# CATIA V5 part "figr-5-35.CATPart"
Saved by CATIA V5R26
Part number: Part1
Bounding box of the stored display mesh (mm): x -39.481 to 85.69, y 0 to 131.399, z 0 to 44
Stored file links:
  D:\_Deepak\CATIA\CATIA V5-6R2016_Deepak\Resources\Part files\Partfiles\c05_catia_v5_6r2016_prt\figr-5-35.CATPart
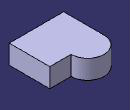
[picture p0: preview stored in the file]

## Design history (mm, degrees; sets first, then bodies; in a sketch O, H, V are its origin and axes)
Body1 (main body)
  Sketch1 on xy-plane, origin (0, 0, 0), H (1, 0, 0), V (0, 1, 0)
    point P1 (-39.4814, 0)
    line L1 (-39.4814, 0) -> (36.6898, 0)
    line L2 (36.6898, 0) -> (36.6898, 93.3015)
    arc A1 centre (-1.4186, 93.3015) radius 38.1084 from (36.6898, 93.3015) to (-39.4814, 95.1659) ccw
    line L3 (-39.4814, 95.1659) -> (-39.4814, 0)
    coincidence: P1 H
    horizontal: L1 H
    vertical: L2 V, L3 V
    tangency: A1 L2
  Pad1: profile Sketch1, direction (0, 0, 1), length 44
  Pad2: profile face of Pad1, direction along edge [face of Pad1 | face of Pad1] reversed, length -49, opposite side length -19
